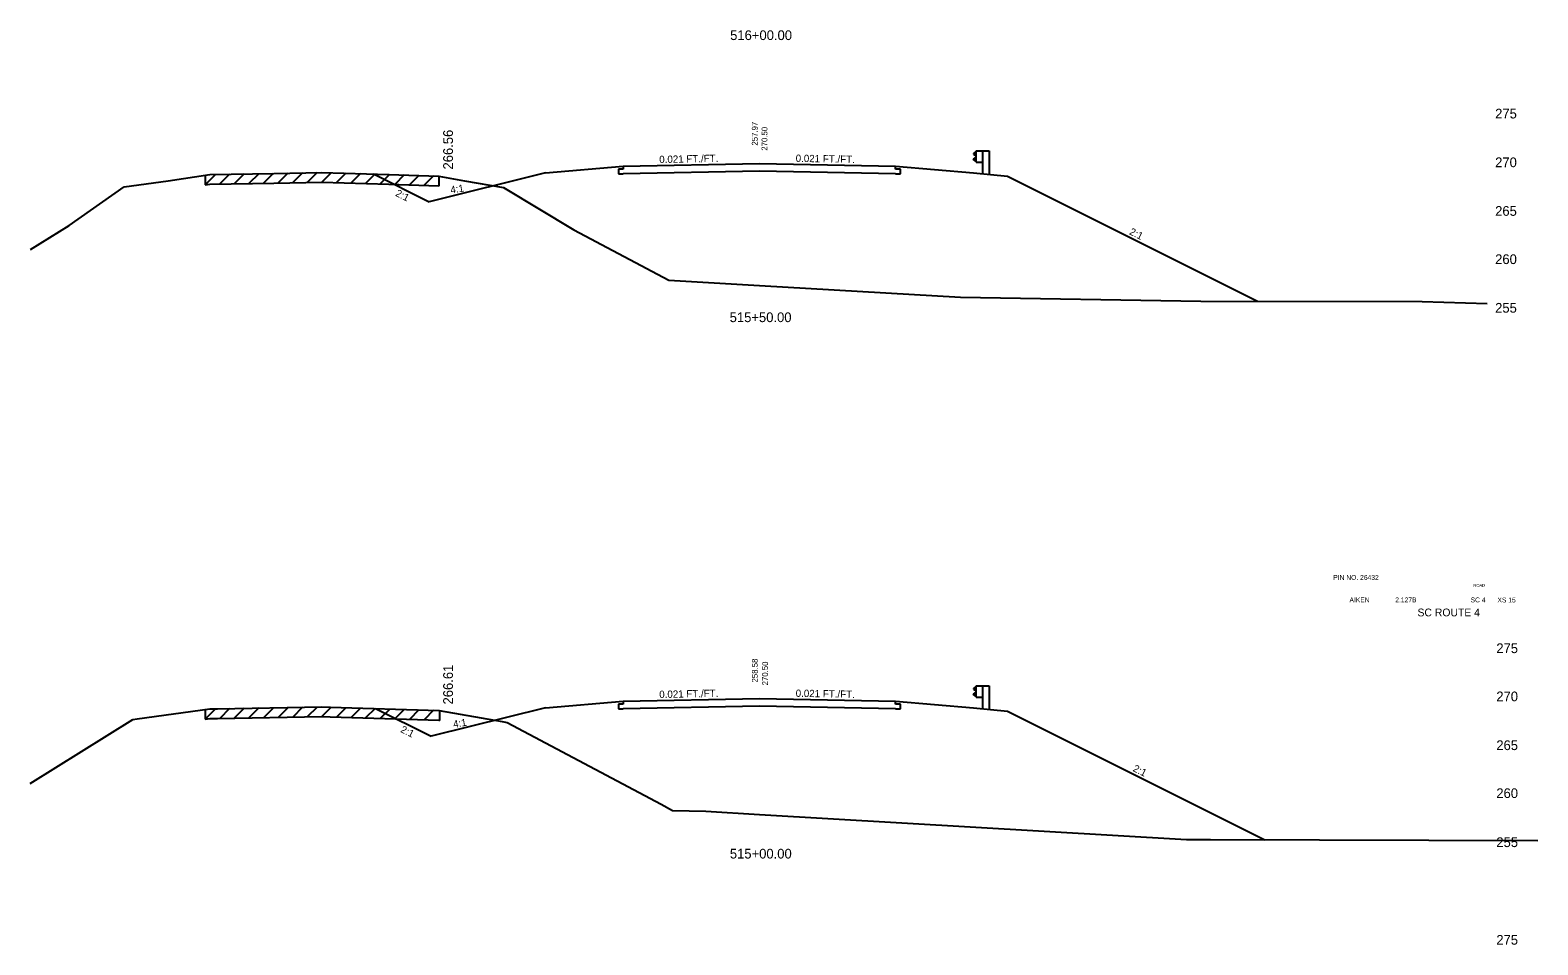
# Model space of a CAD drawing. Extents: x 883 to 1160, y 1002 to 4323.
# Drawn here: x 1005 to 1160, y 2675.2 to 2769.2 of the extents above; entities that cross this region are included whole.
import ezdxf

# ---------------------------------------------------------------- set-up
doc = ezdxf.new("R2010")
doc.units = 0
for name, color, linetype in [('Level 1', 7, 'Continuous'), ('Level 10', 7, 'Continuous'), ('Level 11', 7, 'Continuous'), ('Level 12', 7, 'Continuous'), ('Level 24', 7, 'Continuous'), ('Level 3', 7, 'Continuous'), ('Level 32', 7, 'Continuous'), ('Level 33', 7, 'Continuous'), ('Level 59', 7, 'Continuous'), ('Level 6', 7, 'Continuous'), ('Level 60', 7, 'Continuous'), ('Level 61', 7, 'Continuous'), ('Level 7', 7, 'Continuous')]:
    doc.layers.add(name, color=color, linetype=linetype)

msp = doc.modelspace()

# ---------------------------------------------------------------- linework, layer by layer
at = {"layer": 'Level 11'}
for p, q in [((1066, 2755.21), (1066, 2754.91)), ((1094, 2754.91), (1094, 2755.21)), ((1066, 2754.91), (1065.5, 2754.9)), ((1065.5, 2754.9), (1065.5, 2754.42)), ((1065.5, 2754.42), (1066, 2754.43)), ((1094.5, 2754.9), (1094, 2754.91)), ((1094, 2754.43), (1094.5, 2754.42)), ((1094.5, 2754.42), (1094.5, 2754.9)), ((1066, 2699.91), (1065.5, 2699.9)), ((1065.5, 2699.9), (1065.5, 2699.42)), ((1065.5, 2699.42), (1066, 2699.43)), ((1066, 2700.21), (1066, 2699.91)), ((1094, 2699.91), (1094, 2700.21)), ((1094.5, 2699.9), (1094, 2699.91)), ((1094, 2699.43), (1094.5, 2699.42)), ((1094.5, 2699.42), (1094.5, 2699.9))]:
    msp.add_line(p, q, dxfattribs=at)
at = {"layer": 'Level 12'}
for p, q in [((1080, 2754.72), (1066, 2754.43)), ((1094, 2754.43), (1080, 2754.72)), ((1080, 2699.72), (1066, 2699.43)), ((1094, 2699.43), (1080, 2699.72))]:
    msp.add_line(p, q, dxfattribs=at)
at = {"layer": 'Level 24'}
for p, q in [((1102.27, 2756.72), (1102, 2756.52)), ((1102.27, 2755.63), (1102.27, 2756.79)), ((1102.27, 2756.79), (1102.94, 2756.79)), ((1102.94, 2756.79), (1102.94, 2754.45)), ((1102.94, 2756.79), (1103.6, 2756.79)), ((1103.6, 2756.79), (1103.6, 2754.38)), ((1102, 2756.52), (1102, 2756.47)), ((1102, 2756.47), (1102.27, 2756.27)), ((1102, 2755.95), (1102.27, 2756.15)), ((1102, 2755.9), (1102, 2755.95)), ((1102.27, 2755.7), (1102, 2755.9)), ((1102.27, 2755.63), (1102.94, 2755.63)), ((1102.27, 2701.72), (1102, 2701.52)), ((1102, 2701.52), (1102, 2701.47)), ((1102, 2701.47), (1102.27, 2701.27)), ((1102, 2700.95), (1102.27, 2701.15)), ((1102, 2700.9), (1102, 2700.95)), ((1102.27, 2700.7), (1102, 2700.9)), ((1102.27, 2700.63), (1102.27, 2701.79)), ((1102.27, 2701.79), (1102.94, 2701.79)), ((1102.94, 2701.79), (1102.94, 2699.45)), ((1102.94, 2701.79), (1103.6, 2701.79)), ((1103.6, 2701.79), (1103.6, 2699.38)), ((1102.27, 2700.63), (1102.94, 2700.63))]:
    msp.add_line(p, q, dxfattribs=at)
at = {"layer": 'Level 59'}
for p, q in [((1066, 2755.21), (1080, 2755.5)), ((1080, 2755.5), (1094, 2755.21)), ((1066, 2700.21), (1080, 2700.5)), ((1080, 2700.5), (1094, 2700.21))]:
    msp.add_line(p, q, dxfattribs=at)
at = {"layer": 'Level 6'}
for p, q in [((1058, 2754.54), (1066, 2755.21)), ((1094, 2755.21), (1102, 2754.54)), ((1102, 2754.54), (1105.5, 2754.19)), ((1058, 2699.54), (1066, 2700.21)), ((1094, 2700.21), (1102, 2699.54)), ((1102, 2699.54), (1105.5, 2699.19))]:
    msp.add_line(p, q, dxfattribs=at)
at = {"layer": 'Level 60'}
for p, q in [((1014.7, 2753.11), (1019.25, 2753.73)), ((1019.25, 2753.73), (1023.53, 2754.36)), ((1023.53, 2754.36), (1030.1, 2754.48)), ((1030.1, 2754.48), (1035.01, 2754.58)), ((1035.01, 2754.58), (1041.91, 2754.37)), ((1041.91, 2754.37), (1047.06, 2754.2)), ((1047.06, 2754.2), (1049.68, 2753.73)), ((1049.68, 2753.73), (1053.7, 2753.03)), ((1009.06, 2749.12), (1014.7, 2753.11)), ((1053.7, 2753.03), (1060.93, 2748.69)), ((1005.1, 2746.64), (1009.06, 2749.12)), ((1060.93, 2748.69), (1070.69, 2743.52)), ((1070.69, 2743.52), (1080, 2742.97)), ((1080, 2742.97), (1100.67, 2741.75)), ((1100.67, 2741.75), (1125.38, 2741.36)), ((1125.38, 2741.36), (1148.11, 2741.31)), ((1148.11, 2741.31), (1154.8, 2741.11)), ((1016.05, 2698.42), (1023.53, 2699.43)), ((1023.53, 2699.43), (1024.3, 2699.44)), ((1024.3, 2699.44), (1035.03, 2699.63)), ((1035.03, 2699.63), (1035.87, 2699.6)), ((1035.87, 2699.6), (1047.08, 2699.26)), ((1047.08, 2699.26), (1053.57, 2698.13)), ((1005.05, 2691.74), (1015.59, 2698.33)), ((1015.59, 2698.33), (1016.05, 2698.42)), ((1053.57, 2698.13), (1054.08, 2698.01)), ((1054.08, 2698.01), (1069.9, 2689.63)), ((1069.9, 2689.63), (1071.07, 2688.98)), ((1071.07, 2688.98), (1074.5, 2688.91)), ((1074.5, 2688.91), (1080, 2688.58)), ((1080, 2688.58), (1123.89, 2686)), ((1123.89, 2686), (1126.36, 2685.99)), ((1126.36, 2685.99), (1160, 2685.9))]:
    msp.add_line(p, q, dxfattribs=at)
at = {"layer": 'Level 61'}
for p, q in [((1024.11, 2754.37), (1023.02, 2753.29)), ((1023.02, 2754.29), (1023.02, 2753.29)), ((1023.53, 2753.36), (1030.1, 2753.48)), ((1025.54, 2754.4), (1024.52, 2753.38)), ((1027.04, 2754.43), (1026.02, 2753.41)), ((1028.54, 2754.45), (1027.52, 2753.43)), ((1030.04, 2754.48), (1029.02, 2753.46)), ((1030.1, 2753.48), (1035.01, 2753.58)), ((1031.54, 2754.51), (1030.52, 2753.49)), ((1033.04, 2754.54), (1032.02, 2753.52)), ((1034.54, 2754.57), (1033.52, 2753.55)), ((1035.01, 2753.58), (1041.91, 2753.37)), ((1035.99, 2754.55), (1035.02, 2753.58)), ((1037.49, 2754.51), (1036.52, 2753.54)), ((1038.99, 2754.46), (1038.02, 2753.49)), ((1040.49, 2754.41), (1039.52, 2753.44)), ((1041.99, 2754.37), (1041.02, 2753.4)), ((1043.49, 2754.32), (1042.52, 2753.35)), ((1044.99, 2754.27), (1044.02, 2753.3)), ((1046.49, 2754.22), (1045.52, 2753.25)), ((1047.1, 2753.19), (1047.1, 2754.19)), ((1023.02, 2753.29), (1023.53, 2753.36)), ((1041.91, 2753.37), (1047.06, 2753.2)), ((1047.06, 2753.2), (1047.1, 2753.19)), ((1024.11, 2699.44), (1023.03, 2698.36)), ((1023.03, 2699.36), (1023.03, 2698.36)), ((1025.55, 2699.46), (1024.53, 2698.45)), ((1027.05, 2699.49), (1026.03, 2698.47)), ((1028.55, 2699.52), (1027.53, 2698.5)), ((1030.05, 2699.54), (1029.03, 2698.52)), ((1031.55, 2699.57), (1030.53, 2698.55)), ((1033.05, 2699.59), (1032.03, 2698.58)), ((1034.55, 2699.62), (1033.53, 2698.6)), ((1036, 2699.6), (1035.03, 2698.63)), ((1037.5, 2699.55), (1036.53, 2698.58)), ((1039, 2699.51), (1038.03, 2698.53)), ((1040.5, 2699.46), (1039.53, 2698.49)), ((1042, 2699.41), (1041.03, 2698.44)), ((1043.5, 2699.37), (1042.53, 2698.4)), ((1045, 2699.32), (1044.03, 2698.35)), ((1046.5, 2699.28), (1045.53, 2698.3)), ((1023.03, 2698.36), (1023.53, 2698.43)), ((1023.53, 2698.43), (1024.3, 2698.44)), ((1024.3, 2698.44), (1035.03, 2698.63)), ((1035.03, 2698.63), (1035.87, 2698.6)), ((1035.87, 2698.6), (1047.08, 2698.26)), ((1047.08, 2698.26), (1047.17, 2698.24)), ((1047.17, 2698.24), (1047.17, 2699.24))]:
    msp.add_line(p, q, dxfattribs=at)
at = {"layer": 'Level 7'}
for p, q in [((1040.32, 2754.42), (1046.05, 2751.56)), ((1058, 2754.54), (1046.05, 2751.56)), ((1105.5, 2754.19), (1131.2, 2741.34)), ((1040.55, 2699.46), (1046.25, 2696.61)), ((1058, 2699.54), (1046.25, 2696.61)), ((1105.5, 2699.19), (1131.93, 2685.98))]:
    msp.add_line(p, q, dxfattribs=at)

# ---------------------------------------------------------------- texts
at = {"layer": 'Level 1'}
for s, height, p in [('516+00.00', 1, (1076.99, 2768.19)), ('515+50.00', 1, (1076.94, 2739.19)), ('PIN NO. 26432', 0.5, (1138.97, 2712.69)), ('AIKEN', 0.5, (1140.64, 2710.38)), (' 2.127B', 0.5, (1145.15, 2710.38)), ('SC 4', 0.5, (1153.09, 2710.38)), ('XS 15', 0.5, (1155.85, 2710.37)), ('SC ROUTE 4', 0.8, (1147.63, 2708.94)), ('515+00.00', 1, (1076.96, 2684.04))]:
    msp.add_text(s, height=height, dxfattribs=at).set_placement(p)
at = {"layer": 'Level 10'}
for s, p in [('257.97', (1079.82, 2757.34)), ('258.58', (1079.83, 2702.14))]:
    msp.add_text(s, height=0.6, rotation=90, dxfattribs=at).set_placement(p)
at = {"layer": 'Level 3'}
for s, height, p in [(' 275', 1, (1155.24, 2760.13)), (' 270', 1, (1155.24, 2755.12)), (' 265', 1, (1155.24, 2750.12)), (' 260', 1, (1155.24, 2745.16)), (' 255', 1, (1155.24, 2740.16)), ('ROAD', 0.3, (1153.38, 2711.97)), (' 275', 1, (1155.36, 2705.16)), (' 270', 1, (1155.36, 2700.21)), (' 265', 1, (1155.36, 2695.19)), (' 260', 1, (1155.36, 2690.26)), (' 255', 1, (1155.36, 2685.22)), (' 275', 1, (1155.36, 2675.18))]:
    msp.add_text(s, height=height, dxfattribs=at).set_placement(p)
at = {"layer": 'Level 32'}
for s, rotation, p in [('0.021 FT./FT.', 1.1916, (1069.71, 2755.54)), ('0.021 FT./FT.', 358.8084, (1083.72, 2755.67)), ('2:1', 333.435, (1042.53, 2752.2)), ('4:1', 9.4623, (1048.3, 2752.4)), ('2:1', 333.435, (1117.95, 2748.25)), ('0.021 FT./FT.', 1.1916, (1069.71, 2700.54)), ('0.021 FT./FT.', 358.8084, (1083.72, 2700.67)), ('4:1', 9.4623, (1048.58, 2697.47)), ('2:1', 333.435, (1043.04, 2697.07)), ('2:1', 333.435, (1118.32, 2693.06))]:
    msp.add_text(s, height=0.75, rotation=rotation, dxfattribs=at).set_placement(p)
at = {"layer": 'Level 33'}
for s, p in [('266.56', (1048.5, 2754.88)), ('266.61', (1048.5, 2699.88))]:
    msp.add_text(s, height=1, rotation=90, dxfattribs=at).set_placement(p)
at = {"layer": 'Level 59'}
for p in [(1080.82, 2756.59), (1080.88, 2701.62)]:
    msp.add_text(' 270.50', height=0.6, rotation=90, dxfattribs=at).set_placement(p)

doc.saveas('drawing.dxf')
